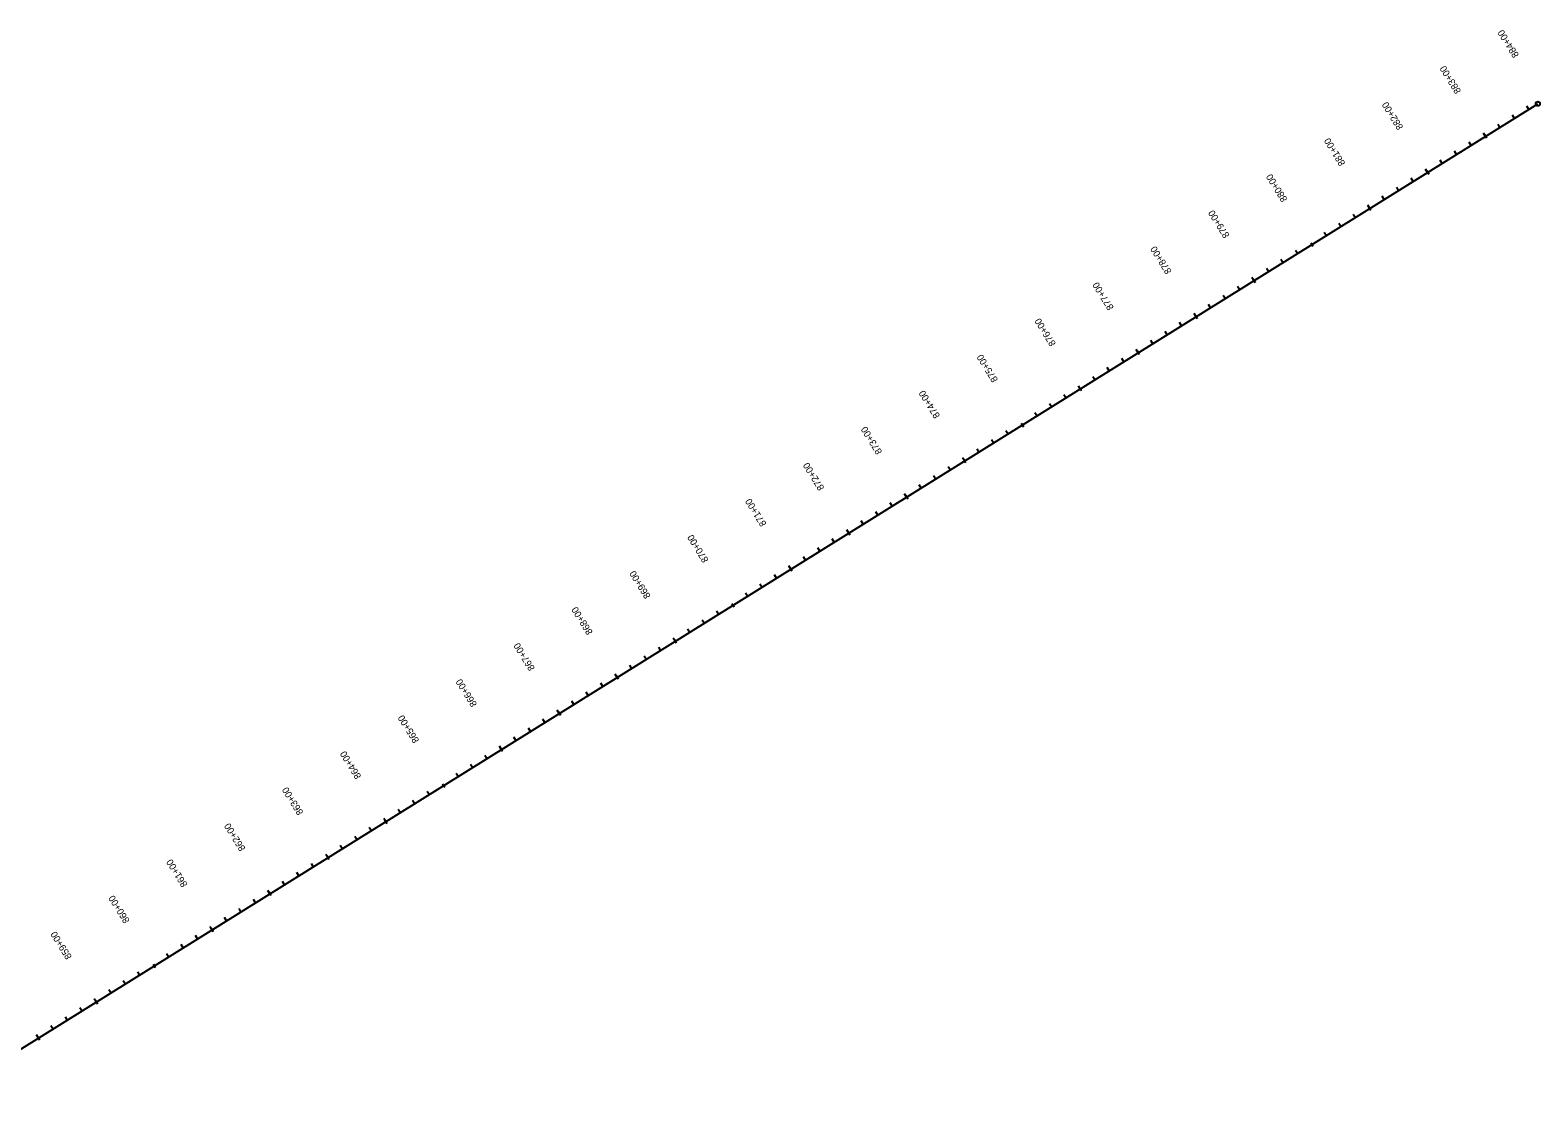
# Model space of a CAD drawing. Extents: x 21481894 to 21524248, y 8295151 to 8330072.
# Drawn here: x 21514637 to 21516848, y 8322927 to 8324507 of the extents above; entities that cross this region are included whole.
import ezdxf

# ---------------------------------------------------------------- set-up
doc = ezdxf.new("R2010")
doc.units = 0
for name, color, linetype in [('Alignment', 7, 'Continuous'), ('Default', 7, 'Continuous'), ('TextAlignment', 7, 'Continuous'), ('TextAlignmentLrg', 7, 'Continuous'), ('TextAlignmentSml', 7, 'Continuous')]:
    doc.layers.add(name, color=color, linetype=linetype)

msp = doc.modelspace()

# ---------------------------------------------------------------- linework, layer by layer
at = {"layer": 'Alignment'}
msp.add_line((21514484.5, 8322927.4), (21516847.7, 8324399.3), dxfattribs=at)
at = {"layer": 'Default'}
msp.add_line((21514484.5, 8322927.4), (21516847.7, 8324399.3), dxfattribs=at)
at = {"layer": 'TextAlignment'}
msp.add_circle((21516847.7, 8324399.3), 3.12, dxfattribs=at)
at = {"layer": 'TextAlignmentLrg'}
for p, q in [((21516770.9, 8324351.5), (21516768.1, 8324356.1)), ((21516686.1, 8324298.6), (21516683.2, 8324303.2)), ((21516601.2, 8324245.7), (21516598.3, 8324250.4)), ((21516514.7, 8324195.5), (21516517.9, 8324190.3)), ((21516431.4, 8324140), (21516428.5, 8324144.6)), ((21516346.5, 8324087.1), (21516343.6, 8324091.8)), ((21516261.7, 8324034.3), (21516258.8, 8324038.9)), ((21516176.8, 8323981.4), (21516173.9, 8323986)), ((21516090.3, 8323931.1), (21516093.5, 8323925.9)), ((21516007, 8323875.6), (21516004.1, 8323880.3)), ((21515922.1, 8323822.8), (21515919.2, 8323827.4)), ((21515837.2, 8323769.9), (21515834.4, 8323774.5)), ((21515752.4, 8323717), (21515749.5, 8323721.7)), ((21515665.9, 8323666.8), (21515669.1, 8323661.6)), ((21515582.6, 8323611.3), (21515579.7, 8323615.9)), ((21515497.7, 8323558.4), (21515494.8, 8323563.1)), ((21515412.8, 8323505.6), (21515409.9, 8323510.2)), ((21515328, 8323452.7), (21515325.1, 8323457.3)), ((21515241.5, 8323402.4), (21515244.7, 8323397.2)), ((21515158.2, 8323347), (21515155.3, 8323351.6)), ((21515073.3, 8323294.1), (21515070.4, 8323298.7)), ((21514988.4, 8323241.2), (21514985.5, 8323245.9)), ((21514903.5, 8323188.4), (21514900.7, 8323193)), ((21514817, 8323138.1), (21514820.3, 8323132.9)), ((21514733.8, 8323082.6), (21514730.9, 8323087.3)), ((21514648.9, 8323029.7), (21514646, 8323034.4))]:
    msp.add_line(p, q, dxfattribs=at)
at = {"layer": 'TextAlignmentSml'}
for p, q in [((21516834.6, 8324391.1), (21516831.7, 8324395.8)), ((21516792.2, 8324364.7), (21516789.3, 8324369.3)), ((21516813.4, 8324377.9), (21516810.5, 8324382.5)), ((21516769.3, 8324354.1), (21516772.6, 8324348.9)), ((21516728.5, 8324325), (21516725.6, 8324329.7)), ((21516749.7, 8324338.3), (21516746.8, 8324342.9)), ((21516684.4, 8324301.2), (21516687.7, 8324296)), ((21516707.3, 8324311.8), (21516704.4, 8324316.5)), ((21516664.8, 8324285.4), (21516662, 8324290)), ((21516622.4, 8324258.9), (21516619.5, 8324263.6)), ((21516643.6, 8324272.2), (21516640.7, 8324276.8)), ((21516580, 8324232.5), (21516577.1, 8324237.1)), ((21516599.6, 8324248.3), (21516602.8, 8324243.1)), ((21516558.7, 8324219.3), (21516555.9, 8324223.9)), ((21516514.7, 8324195.5), (21516517.9, 8324190.3)), ((21516537.5, 8324206.1), (21516534.6, 8324210.7)), ((21516473.9, 8324166.4), (21516471, 8324171.1)), ((21516495.1, 8324179.6), (21516492.2, 8324184.3)), ((21516452.6, 8324153.2), (21516449.7, 8324157.8)), ((21516410.2, 8324126.8), (21516407.3, 8324131.4)), ((21516429.8, 8324142.6), (21516433, 8324137.4)), ((21516367.8, 8324100.3), (21516364.9, 8324105)), ((21516389, 8324113.6), (21516386.1, 8324118.2)), ((21516344.9, 8324089.7), (21516348.2, 8324084.5)), ((21516304.1, 8324060.7), (21516301.2, 8324065.3)), ((21516325.3, 8324073.9), (21516322.4, 8324078.5)), ((21516260, 8324036.9), (21516263.3, 8324031.7)), ((21516282.9, 8324047.5), (21516280, 8324052.1)), ((21516240.4, 8324021), (21516237.5, 8324025.7)), ((21516198, 8323994.6), (21516195.1, 8323999.2)), ((21516219.2, 8324007.8), (21516216.3, 8324012.5)), ((21516155.6, 8323968.2), (21516152.7, 8323972.8)), ((21516175.2, 8323984), (21516178.4, 8323978.8)), ((21516134.3, 8323955), (21516131.4, 8323959.6)), ((21516090.3, 8323931.1), (21516093.5, 8323925.9)), ((21516113.1, 8323941.7), (21516110.2, 8323946.4)), ((21516049.4, 8323902.1), (21516046.6, 8323906.7)), ((21516070.7, 8323915.3), (21516067.8, 8323919.9)), ((21516028.2, 8323888.9), (21516025.3, 8323893.5)), ((21515985.8, 8323862.4), (21515982.9, 8323867.1)), ((21516005.4, 8323878.2), (21516008.6, 8323873.1)), ((21515943.3, 8323836), (21515940.5, 8323840.6)), ((21515964.6, 8323849.2), (21515961.7, 8323853.8)), ((21515920.5, 8323825.4), (21515923.7, 8323820.2)), ((21515879.7, 8323796.3), (21515876.8, 8323801)), ((21515900.9, 8323809.6), (21515898, 8323814.2)), ((21515835.6, 8323772.5), (21515838.9, 8323767.3)), ((21515858.5, 8323783.1), (21515855.6, 8323787.8)), ((21515816, 8323756.7), (21515813.1, 8323761.3)), ((21515773.6, 8323730.3), (21515770.7, 8323734.9)), ((21515794.8, 8323743.5), (21515791.9, 8323748.1)), ((21515731.1, 8323703.8), (21515728.3, 8323708.5)), ((21515750.7, 8323719.6), (21515754, 8323714.4)), ((21515688.7, 8323677.4), (21515685.8, 8323682)), ((21515709.9, 8323690.6), (21515707, 8323695.2)), ((21515665.9, 8323666.8), (21515669.1, 8323661.6)), ((21515625, 8323637.7), (21515622.2, 8323642.4)), ((21515646.3, 8323651), (21515643.4, 8323655.6)), ((21515603.8, 8323624.5), (21515600.9, 8323629.2)), ((21515561.4, 8323598.1), (21515558.5, 8323602.7)), ((21515581, 8323613.9), (21515584.2, 8323608.7)), ((21515518.9, 8323571.7), (21515516.1, 8323576.3)), ((21515540.2, 8323584.9), (21515537.3, 8323589.5)), ((21515476.5, 8323545.2), (21515473.6, 8323549.9)), ((21515496.1, 8323561), (21515499.3, 8323555.8)), ((21515455.3, 8323532), (21515452.4, 8323536.6)), ((21515411.2, 8323508.2), (21515414.5, 8323503)), ((21515434.1, 8323518.8), (21515431.2, 8323523.4)), ((21515370.4, 8323479.1), (21515367.5, 8323483.8)), ((21515391.6, 8323492.4), (21515388.7, 8323497)), ((21515349.2, 8323465.9), (21515346.3, 8323470.6)), ((21515306.7, 8323439.5), (21515303.8, 8323444.1)), ((21515326.3, 8323455.3), (21515329.6, 8323450.1)), ((21515264.3, 8323413), (21515261.4, 8323417.7)), ((21515285.5, 8323426.3), (21515282.6, 8323430.9)), ((21515241.5, 8323402.4), (21515244.7, 8323397.2)), ((21515200.6, 8323373.4), (21515197.7, 8323378)), ((21515221.9, 8323386.6), (21515219, 8323391.2)), ((21515179.4, 8323360.2), (21515176.5, 8323364.8)), ((21515137, 8323333.7), (21515134.1, 8323338.4)), ((21515156.6, 8323349.6), (21515159.8, 8323344.4)), ((21515094.5, 8323307.3), (21515091.6, 8323311.9)), ((21515115.8, 8323320.5), (21515112.9, 8323325.2)), ((21515052.1, 8323280.9), (21515049.2, 8323285.5)), ((21515071.7, 8323296.7), (21515074.9, 8323291.5)), ((21515030.9, 8323267.7), (21515028, 8323272.3)), ((21514986.8, 8323243.8), (21514990, 8323238.6)), ((21515009.6, 8323254.4), (21515006.8, 8323259.1)), ((21514946, 8323214.8), (21514943.1, 8323219.4)), ((21514967.2, 8323228), (21514964.3, 8323232.6)), ((21514924.8, 8323201.6), (21514921.9, 8323206.2)), ((21514882.3, 8323175.1), (21514879.4, 8323179.8)), ((21514901.9, 8323191), (21514905.2, 8323185.8)), ((21514839.9, 8323148.7), (21514837, 8323153.3)), ((21514861.1, 8323161.9), (21514858.2, 8323166.6)), ((21514817, 8323138.1), (21514820.3, 8323132.9)), ((21514776.2, 8323109.1), (21514773.3, 8323113.7)), ((21514797.4, 8323122.3), (21514794.6, 8323126.9)), ((21514732.2, 8323085.2), (21514735.4, 8323080)), ((21514755, 8323095.8), (21514752.1, 8323100.5)), ((21514712.6, 8323069.4), (21514709.7, 8323074)), ((21514670.1, 8323043), (21514667.2, 8323047.6)), ((21514691.3, 8323056.2), (21514688.5, 8323060.8)), ((21514647.3, 8323032.3), (21514650.5, 8323027.2))]:
    msp.add_line(p, q, dxfattribs=at)

# ---------------------------------------------------------------- texts
at = {"layer": 'TextAlignmentLrg'}
for s, p in [('880+00', (21516480.9, 8324259.2)), ('875+00', (21516056.5, 8323994.8)), ('870+00', (21515632.1, 8323730.5)), ('865+00', (21515207.7, 8323466.1)), ('860+00', (21514783.3, 8323201.8))]:
    msp.add_text(s, height=10.02, rotation=121.9168, dxfattribs=at).set_placement(p)
at = {"layer": 'TextAlignmentSml'}
for s, rotation, p in [('884+00', 121.9111, (21516820.4, 8324470.6)), ('883+00', 121.9168, (21516735.5, 8324417.8)), ('882+00', 121.9168, (21516650.7, 8324364.9)), ('881+00', 121.9168, (21516565.8, 8324312)), ('880+00', 121.9168, (21516480.9, 8324259.2)), ('879+00', 121.9168, (21516396, 8324206.3)), ('878+00', 121.9168, (21516311.1, 8324153.4)), ('877+00', 121.9168, (21516226.3, 8324100.6)), ('876+00', 121.9168, (21516141.4, 8324047.7)), ('875+00', 121.9168, (21516056.5, 8323994.8)), ('874+00', 121.9168, (21515971.6, 8323942)), ('873+00', 121.9168, (21515886.7, 8323889.1)), ('872+00', 121.9168, (21515801.8, 8323836.2)), ('871+00', 121.9168, (21515717, 8323783.4)), ('870+00', 121.9168, (21515632.1, 8323730.5)), ('869+00', 121.9168, (21515547.2, 8323677.6)), ('868+00', 121.9168, (21515462.3, 8323624.7)), ('867+00', 121.9168, (21515377.4, 8323571.9)), ('866+00', 121.9168, (21515292.6, 8323519)), ('865+00', 121.9168, (21515207.7, 8323466.1)), ('864+00', 121.9168, (21515122.8, 8323413.3)), ('863+00', 121.9168, (21515037.9, 8323360.4)), ('862+00', 121.9168, (21514953, 8323307.5)), ('861+00', 121.9168, (21514868.1, 8323254.7)), ('860+00', 121.9168, (21514783.3, 8323201.8)), ('859+00', 121.9168, (21514698.4, 8323148.9))]:
    msp.add_text(s, height=10.02, rotation=rotation, dxfattribs=at).set_placement(p)

doc.saveas('drawing.dxf')
